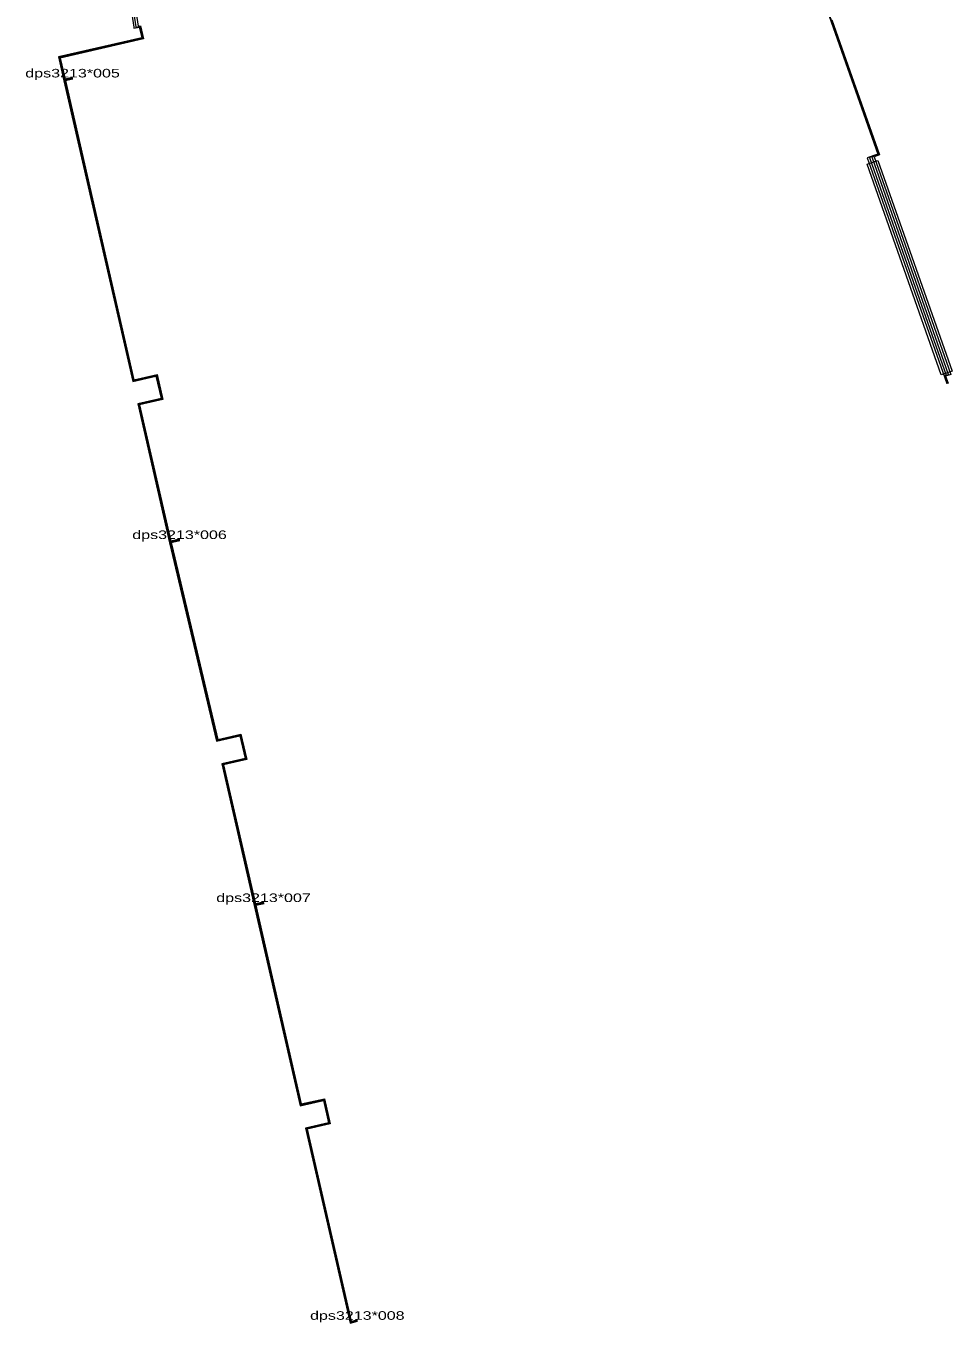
# Model space of a CAD drawing. Extents: x -473467 to -473049, y -1106745 to -1106181.
# Drawn here: x -473357.1 to -473259.8, y -1106716.6 to -1106580.3 of the extents above; entities that cross this region are included whole.
import ezdxf
from ezdxf.enums import TextEntityAlignment as Align

# ---------------------------------------------------------------- set-up
doc = ezdxf.new("R2010")
doc.units = 0
doc.header["$LTSCALE"] = 0.36
doc.layers.add('11', color=7, linetype='Continuous', lineweight=13)
doc.layers.add('17', color=7, linetype='Continuous', lineweight=13)
doc.layers.add('19', color=7, linetype='Continuous')

msp = doc.modelspace()

# ---------------------------------------------------------------- linework, layer by layer
at = {"layer": '11'}
for points in [[(-473351.021, -1106546.248), (-473351.224, -1106546.383), (-473356.119, -1106549.637), (-473348.2, -1106561.55), (-473345.319, -1106580.369), (-473345.132, -1106580.332), (-473345.132, -1106580.334)], [(-473348.658, -1106561.727), (-473345.79, -1106580.462), (-473345.766, -1106580.559), (-473345.206, -1106580.451), (-473344.932, -1106581.583), (-473353.692, -1106583.589), (-473353.115, -1106586.097), (-473352.181, -1106585.888), (-473353.115, -1106586.097), (-473345.888, -1106617.682), (-473343.451, -1106617.124), (-473342.911, -1106619.486), (-473345.348, -1106620.044), (-473342.013, -1106634.637), (-473340.943, -1106634.389), (-473342.013, -1106634.637), (-473337.076, -1106655.502), (-473334.638, -1106654.943), (-473334.096, -1106657.306), (-473336.533, -1106657.864), (-473333.122, -1106672.747), (-473332.101, -1106672.542), (-473333.122, -1106672.747), (-473328.299, -1106693.795), (-473325.862, -1106693.237), (-473325.321, -1106695.599), (-473327.758, -1106696.157), (-473323.064, -1106716.637), (-473322.266, -1106716.441)], [(-473348.429, -1106561.639), (-473345.554, -1106580.415), (-473345.546, -1106580.462), (-473345.169, -1106580.392), (-473344.872, -1106581.62), (-473353.632, -1106583.627), (-473353.078, -1106586.038), (-473352.2, -1106585.841), (-473353.078, -1106586.038), (-473345.851, -1106617.622), (-473343.413, -1106617.064), (-473342.851, -1106619.523), (-473345.289, -1106620.082), (-473341.976, -1106634.577), (-473340.96, -1106634.343), (-473341.976, -1106634.577), (-473337.039, -1106655.442), (-473334.6, -1106654.883), (-473334.036, -1106657.343), (-473336.473, -1106657.902), (-473333.085, -1106672.688), (-473332.116, -1106672.487), (-473333.085, -1106672.688), (-473328.261, -1106693.735), (-473325.825, -1106693.177), (-473325.261, -1106695.637), (-473327.698, -1106696.195), (-473323.026, -1106716.567), (-473322.277, -1106716.392)], [(-473272.737, -1106579.3), (-473267.635, -1106593.795), (-473268.732, -1106594.181), (-473268.389, -1106595.156), (-473260.379, -1106617.917)], [(-473272.712, -1106579.222), (-473267.571, -1106593.826), (-473268.489, -1106594.148), (-473268.451, -1106594.254), (-473260.444, -1106617.011), (-473260.623, -1106617.074), (-473260.332, -1106617.899)], [(-473272.44, -1106579.69), (-473267.442, -1106593.886), (-473268.003, -1106594.083), (-473259.991, -1106616.851), (-473259.958, -1106616.946), (-473260.495, -1106617.135), (-473260.238, -1106617.866)], [(-473345.132, -1106580.334), (-473344.811, -1106581.657), (-473353.572, -1106583.664), (-473353.04, -1106585.978), (-473352.214, -1106585.793), (-473353.04, -1106585.978), (-473345.813, -1106617.563), (-473343.375, -1106617.004), (-473342.791, -1106619.561), (-473345.229, -1106620.12), (-473341.938, -1106634.517), (-473340.97, -1106634.294), (-473341.938, -1106634.517), (-473341.842, -1106634.921), (-473338.417, -1106649.4)], [(-473345.083, -1106580.322), (-473344.751, -1106581.695), (-473353.512, -1106583.702), (-473353.003, -1106585.919), (-473352.215, -1106585.742), (-473353.003, -1106585.919), (-473345.776, -1106617.503), (-473343.338, -1106616.944), (-473342.732, -1106619.598), (-473345.169, -1106620.157), (-473341.9, -1106634.458), (-473340.976, -1106634.245), (-473341.9, -1106634.458), (-473341.795, -1106634.904), (-473338.37, -1106649.379)], [(-473272.486, -1106579.711), (-473267.506, -1106593.856), (-473268.246, -1106594.116), (-473268.225, -1106594.174), (-473260.217, -1106616.932), (-473260.2, -1106616.979), (-473260.559, -1106617.105), (-473260.284, -1106617.886)], [(-473338.417, -1106649.4), (-473337.002, -1106655.382), (-473334.563, -1106654.824), (-473333.977, -1106657.381), (-473336.413, -1106657.939), (-473333.047, -1106672.629), (-473332.143, -1106672.442), (-473333.047, -1106672.629), (-473328.224, -1106693.675), (-473325.787, -1106693.117), (-473325.201, -1106695.674), (-473327.638, -1106696.233), (-473323.015, -1106716.406), (-473323.004, -1106716.455), (-473322.992, -1106716.504), (-473322.29, -1106716.343)], [(-473338.37, -1106649.379), (-473336.964, -1106655.323), (-473334.525, -1106654.764), (-473333.917, -1106657.418), (-473336.354, -1106657.977), (-473333.009, -1106672.571), (-473332.153, -1106672.394), (-473333.009, -1106672.571), (-473328.186, -1106693.616), (-473325.749, -1106693.057), (-473325.141, -1106695.712), (-473327.578, -1106696.27), (-473322.955, -1106716.444), (-473322.3, -1106716.294)]]:
    msp.add_lwpolyline(points, dxfattribs=at)
at = {"layer": '17'}
msp.add_lwpolyline([(-473260.956, -1106617.001), (-473268.748, -1106594.858), (-473267.616, -1106594.46), (-473259.824, -1106616.602)], close=True, dxfattribs=at)

# ---------------------------------------------------------------- texts
at = {"layer": '19', "width": 1.4}
for s, p in [('dps3213*005', (-473352.215, -1106585.742)), ('dps3213*006', (-473340.976, -1106634.245)), ('dps3213*007', (-473332.153, -1106672.394)), ('dps3213*008', (-473322.3, -1106716.294))]:
    msp.add_text(s, height=0.9, dxfattribs=at).set_placement(p, align=Align.CENTER)

doc.saveas('drawing.dxf')
